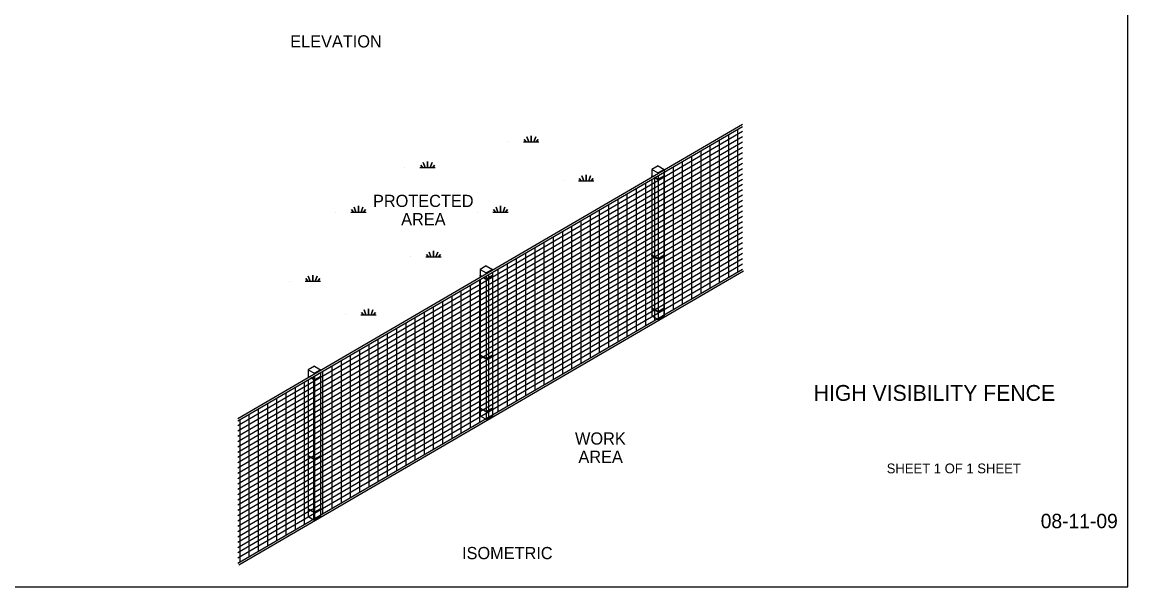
# Model space of a CAD drawing. Extents: x 99862 to 103151, y 100000 to 102076.
# Drawn here: x 101337 to 103151, y 100000 to 100926 of the extents above; entities that cross this region are included whole.
import ezdxf

# ---------------------------------------------------------------- set-up
doc = ezdxf.new("R2010")
doc.units = 0
for name, color, linetype in [('Level 1', 7, 'Continuous'), ('Level 10', 7, 'Continuous'), ('Level 11', 7, 'Continuous'), ('Level 15', 7, 'Continuous'), ('Level 20', 7, 'Continuous'), ('Level 31', 7, 'Continuous'), ('Level 38', 7, 'Continuous'), ('Level 62', 7, 'Continuous'), ('Level 9', 7, 'Continuous')]:
    doc.layers.add(name, color=color, linetype=linetype)

msp = doc.modelspace()

# ---------------------------------------------------------------- linework, layer by layer
at = {"layer": 'Level 1'}
msp.add_lwpolyline([(99862, 99999.5), (103151, 99999.5), (103151, 102075.5), (99862, 102075.5)], close=True, dxfattribs=at)
at = {"layer": 'Level 10'}
msp.add_line((101815.7, 100208.6), (101815.7, 100208.7), dxfattribs=at)
at = {"layer": 'Level 11'}
for p, q in [((102372.4, 100672.9), (102370.3, 100674.1)), ((102370.3, 100673.4), (102370.3, 100674.1)), ((102371.7, 100672.6), (102370.3, 100673.4)), ((102380.3, 100667.6), (102374.5, 100670.9)), ((102380.3, 100668.3), (102375.2, 100671.3)), ((102390.3, 100674.1), (102380.3, 100668.3)), ((102390.3, 100673.4), (102380.3, 100667.6)), ((102390.3, 100673.4), (102390.3, 100674.1)), ((102380.3, 100538), (102370.3, 100543.7)), ((102370.3, 100543), (102370.3, 100543.7)), ((102380.3, 100537.2), (102370.3, 100543)), ((102390.3, 100543.7), (102380.3, 100538)), ((102390.3, 100543), (102380.3, 100537.2)), ((102390.3, 100543), (102390.3, 100543.7)), ((102091, 100508.8), (102088.5, 100510.2)), ((102088.5, 100509.5), (102088.5, 100510.2)), ((102098.5, 100503.7), (102093.3, 100506.7)), ((102098.5, 100504.5), (102093.9, 100507.1)), ((102108.5, 100510.2), (102098.5, 100504.5)), ((102108.5, 100509.5), (102098.5, 100503.7)), ((102108.5, 100509.5), (102108.5, 100510.2)), ((102380.3, 100451), (102370.3, 100456.8)), ((102370.3, 100456.8), (102370.3, 100456.1)), ((102380.3, 100450.3), (102370.3, 100456.1)), ((102390.3, 100456.8), (102380.3, 100451)), ((102390.3, 100456.1), (102380.3, 100450.3)), ((102390.3, 100456.1), (102390.3, 100456.8)), ((102098.5, 100374.1), (102088.5, 100379.9)), ((102108.5, 100379.9), (102098.5, 100374.1)), ((102108.5, 100379.1), (102108.5, 100379.9)), ((102098.5, 100373.4), (102088.5, 100379.1)), ((102108.5, 100379.1), (102098.5, 100373.4)), ((101808.4, 100344), (101806.6, 100345)), ((101807.8, 100343.6), (101806.6, 100344.3)), ((101826.6, 100345), (101816.6, 100339.2)), ((101826.6, 100344.3), (101816.6, 100338.5)), ((101826.6, 100344.3), (101826.6, 100345)), ((101816.6, 100338.5), (101810.8, 100341.9)), ((101816.6, 100339.2), (101811.4, 100342.3)), ((102098.5, 100287.2), (102088.5, 100293)), ((102088.5, 100292.2), (102088.5, 100293)), ((102098.5, 100286.5), (102088.5, 100292.2)), ((102108.5, 100293), (102098.5, 100287.2)), ((102108.5, 100292.2), (102098.5, 100286.5)), ((102108.5, 100292.2), (102108.5, 100293)), ((101810, 100212.7), (101806.6, 100214.7)), ((101806.6, 100213.9), (101806.6, 100214.7)), ((101809.4, 100212.3), (101806.6, 100213.9)), ((101816.6, 100208.2), (101810.6, 100211.6)), ((101816.6, 100208.9), (101811.3, 100212)), ((101826.6, 100214.7), (101816.6, 100208.9)), ((101826.6, 100213.9), (101816.6, 100208.2)), ((101826.6, 100213.9), (101826.6, 100214.7)), ((101816.6, 100122), (101806.6, 100127.7)), ((101806.6, 100127.7), (101806.6, 100127)), ((101816.6, 100121.2), (101806.6, 100127)), ((101826.6, 100127.7), (101816.6, 100122)), ((101826.6, 100127), (101816.6, 100121.2)), ((101826.6, 100127), (101826.6, 100127.7))]:
    msp.add_line(p, q, dxfattribs=at)
at = {"layer": 'Level 31'}
for p, q in [((102134.8, 100729.7), (102134.8, 100729.7)), ((101964.8, 100687.7), (101964.8, 100687.7)), ((102225, 100665.8), (102225, 100665.8)), ((101851.5, 100614.6), (101851.5, 100614.6)), ((102084.3, 100614.6), (102084.3, 100614.6)), ((101974.4, 100540.9), (101974.4, 100540.9)), ((101776.4, 100501.3), (101776.4, 100501.3)), ((101867.9, 100446), (101867.9, 100446))]:
    msp.add_line(p, q, dxfattribs=at)
for points in [[(102159.8, 100729.7), (102164, 100729.7), (102160.9, 100733.7), (102164, 100729.7), (102168.1, 100729.7), (102165, 100737.8), (102168.1, 100729.7), (102172.3, 100729.7), (102172.3, 100739.7), (102172.3, 100729.7), (102176.5, 100729.7), (102179.6, 100737.8), (102176.5, 100729.7), (102180.6, 100729.7), (102183.7, 100733.7), (102180.6, 100729.7), (102184.8, 100729.7)], [(101989.8, 100687.7), (101994, 100687.7), (101990.9, 100691.7), (101994, 100687.7), (101998.1, 100687.7), (101995, 100695.8), (101998.1, 100687.7), (102002.3, 100687.7), (102002.3, 100697.6), (102002.3, 100687.7), (102006.5, 100687.7), (102009.6, 100695.8), (102006.5, 100687.7), (102010.6, 100687.7), (102013.7, 100691.7), (102010.6, 100687.7), (102014.8, 100687.7)], [(102249.9, 100665.8), (102254.1, 100665.8), (102251, 100669.9), (102254.1, 100665.8), (102258.3, 100665.8), (102255.2, 100673.9), (102258.3, 100665.8), (102262.4, 100665.8), (102262.4, 100675.8), (102262.4, 100665.8), (102266.6, 100665.8), (102269.7, 100673.9), (102266.6, 100665.8), (102270.8, 100665.8), (102273.9, 100669.9), (102270.8, 100665.8), (102274.9, 100665.8)], [(101876.5, 100614.6), (101880.7, 100614.6), (101877.6, 100618.6), (101880.7, 100614.6), (101884.8, 100614.6), (101881.7, 100622.7), (101884.8, 100614.6), (101889, 100614.6), (101889, 100624.6), (101889, 100614.6), (101893.1, 100614.6), (101896.3, 100622.7), (101893.1, 100614.6), (101897.3, 100614.6), (101900.4, 100618.6), (101897.3, 100614.6), (101901.5, 100614.6)], [(102109.3, 100614.6), (102113.5, 100614.6), (102110.4, 100618.6), (102113.5, 100614.6), (102117.6, 100614.6), (102114.5, 100622.7), (102117.6, 100614.6), (102121.8, 100614.6), (102121.8, 100624.6), (102121.8, 100614.6), (102126, 100614.6), (102129.1, 100622.7), (102126, 100614.6), (102130.1, 100614.6), (102133.2, 100618.6), (102130.1, 100614.6), (102134.3, 100614.6)], [(101999.4, 100540.9), (102003.5, 100540.9), (102000.4, 100544.9), (102003.5, 100540.9), (102007.7, 100540.9), (102004.6, 100549), (102007.7, 100540.9), (102011.9, 100540.9), (102011.9, 100550.8), (102011.9, 100540.9), (102016, 100540.9), (102019.1, 100549), (102016, 100540.9), (102020.2, 100540.9), (102023.3, 100544.9), (102020.2, 100540.9), (102024.4, 100540.9)], [(101801.4, 100501.3), (101805.6, 100501.3), (101802.5, 100505.3), (101805.6, 100501.3), (101809.7, 100501.3), (101806.6, 100509.4), (101809.7, 100501.3), (101813.9, 100501.3), (101813.9, 100511.2), (101813.9, 100501.3), (101818, 100501.3), (101821.2, 100509.4), (101818, 100501.3), (101822.2, 100501.3), (101825.3, 100505.3), (101822.2, 100501.3), (101826.4, 100501.3)], [(101892.9, 100446), (101897, 100446), (101893.9, 100450), (101897, 100446), (101901.2, 100446), (101898.1, 100454.1), (101901.2, 100446), (101905.4, 100446), (101905.4, 100455.9), (101905.4, 100446), (101909.5, 100446), (101912.6, 100454.1), (101909.5, 100446), (101913.7, 100446), (101916.8, 100450), (101913.7, 100446), (101917.9, 100446)]]:
    msp.add_lwpolyline(points, dxfattribs=at)
at = {"layer": 'Level 38'}
for p, q in [((102380.3, 100690.4), (102370.3, 100684.6)), ((102380.3, 100690.4), (102390.3, 100684.6)), ((102370.3, 100684.6), (102380.3, 100678.8)), ((102370.3, 100684.6), (102370.3, 100671.7)), ((102390.3, 100684.6), (102380.3, 100678.8)), ((102380.3, 100678.8), (102380.3, 100677.5)), ((102380.3, 100674.3), (102380.3, 100668.3)), ((102390.3, 100684.6), (102390.3, 100683.4)), ((102390.3, 100683.4), (102390.3, 100674.1)), ((102390.3, 100673.4), (102390.3, 100543.7)), ((102370.3, 100668.2), (102370.3, 100543.7)), ((102380.3, 100667.6), (102380.3, 100538)), ((102370.3, 100543), (102370.3, 100456.8)), ((102390.3, 100543), (102390.3, 100456.8)), ((102098.5, 100526.2), (102088.5, 100520.5)), ((102098.5, 100526.2), (102108.5, 100520.5)), ((102380.3, 100537.2), (102380.3, 100451)), ((102088.5, 100520.5), (102098.5, 100514.7)), ((102088.5, 100520.5), (102088.5, 100507.4)), ((102108.5, 100520.5), (102098.5, 100514.7)), ((102098.5, 100514.7), (102098.5, 100513.2)), ((102098.5, 100509.9), (102098.5, 100504.5)), ((102108.5, 100520.5), (102108.5, 100519)), ((102108.5, 100515.5), (102108.5, 100379.9)), ((102088.5, 100504.1), (102088.5, 100280.2)), ((102098.5, 100503.7), (102098.5, 100374.1)), ((102370.3, 100456.1), (102370.3, 100444.1)), ((102390.3, 100456.1), (102390.3, 100446.2)), ((102370.3, 100444.1), (102378.6, 100439.4)), ((102379.4, 100438.8), (102380.3, 100438.3)), ((102380.3, 100450.3), (102380.3, 100440.4)), ((102390.3, 100444.1), (102380.3, 100438.3)), ((102380.3, 100439.4), (102380.3, 100438.3)), ((102390.3, 100445.2), (102390.3, 100444.1)), ((102098.5, 100373.4), (102098.5, 100287.2)), ((102108.5, 100379.1), (102108.5, 100293)), ((101816.6, 100361.6), (101806.6, 100355.8)), ((101806.6, 100355.8), (101816.6, 100350)), ((101806.6, 100355.8), (101806.6, 100343)), ((101816.6, 100361.6), (101826.6, 100355.8)), ((101826.6, 100355.8), (101816.6, 100350)), ((101816.6, 100350), (101816.6, 100348.8)), ((101816.6, 100345.6), (101816.6, 100339.2)), ((101826.6, 100355.8), (101826.6, 100354.7)), ((101826.6, 100351.4), (101826.6, 100343.9)), ((101806.6, 100339.7), (101806.6, 100127.7)), ((101816.6, 100338.5), (101816.6, 100208.9)), ((101826.6, 100342.5), (101826.6, 100214.7)), ((102108.5, 100292.2), (102108.5, 100281.8)), ((102088.5, 100280.2), (102096.4, 100275.6)), ((102097.9, 100274.7), (102098.5, 100274.4)), ((102098.5, 100286.5), (102098.5, 100276)), ((102108.5, 100280.2), (102098.5, 100274.4)), ((102098.5, 100275), (102098.5, 100274.4)), ((102108.5, 100280.8), (102108.5, 100280.2)), ((101816.6, 100208.2), (101816.6, 100122)), ((101826.6, 100213.9), (101826.6, 100127.7)), ((101806.6, 100127), (101806.6, 100115.2)), ((101826.6, 100127), (101826.6, 100117.5)), ((101806.6, 100114.9), (101816.6, 100109.1)), ((101815.4, 100109.9), (101816.6, 100109.1)), ((101816.6, 100121.2), (101816.6, 100111.6)), ((101826.6, 100114.9), (101816.6, 100109.1)), ((101816.6, 100110.6), (101816.6, 100109.1)), ((101826.6, 100116.5), (101826.6, 100114.9))]:
    msp.add_line(p, q, dxfattribs=at)
at = {"layer": 'Level 9'}
for p, q in [((102518.7, 100758.3), (101690.9, 100275.5)), ((101690.9, 100272.2), (102518.7, 100755)), ((101690.9, 100264.3), (102518.7, 100747.1)), ((102510.8, 100750.4), (102510.8, 100516.5)), ((101690.9, 100255.6), (102518.7, 100738.4)), ((101690.9, 100246.9), (102518.7, 100729.7)), ((102480.5, 100732.7), (102480.5, 100498.8)), ((102495.6, 100741.6), (102495.6, 100507.6)), ((101690.9, 100238.2), (102518.7, 100721)), ((101690.9, 100229.5), (102518.7, 100712.3)), ((102435.1, 100706.3), (102435.1, 100472.3)), ((102450.3, 100715.1), (102450.3, 100481.2)), ((102450.3, 100715.1), (102450.3, 100658.3)), ((102465.4, 100723.9), (102465.4, 100490)), ((102465.4, 100723.9), (102465.4, 100667.2)), ((101690.9, 100220.8), (102518.7, 100703.6)), ((101690.9, 100212.1), (102518.7, 100694.9)), ((102404.9, 100688.6), (102404.9, 100454.7)), ((102420, 100697.5), (102420, 100463.5)), ((101690.9, 100203.4), (102518.7, 100686.2)), ((101690.9, 100194.8), (102518.7, 100677.5)), ((102374.6, 100671), (102374.6, 100437.1)), ((102389.8, 100679.8), (102389.8, 100445.9)), ((101690.9, 100186.1), (102518.7, 100668.8)), ((101690.9, 100177.4), (102518.7, 100660.2)), ((102344.4, 100653.4), (102344.4, 100419.4)), ((102359.5, 100662.2), (102359.5, 100428.2)), ((101690.9, 100168.7), (102518.7, 100651.5)), ((101690.9, 100160), (102518.7, 100642.8)), ((101690.9, 100151.3), (102518.7, 100634.1)), ((102314.1, 100635.7), (102314.1, 100401.8)), ((102314.1, 100635.7), (102314.1, 100578.9)), ((102329.3, 100644.5), (102329.3, 100410.6)), ((101690.9, 100142.6), (102518.7, 100625.4)), ((101690.9, 100133.9), (102518.7, 100616.7)), ((102283.9, 100618.1), (102283.9, 100384.1)), ((102283.9, 100618.1), (102283.9, 100561.3)), ((102299, 100626.9), (102299, 100393)), ((102299, 100626.9), (102299, 100570.1)), ((101690.9, 100125.2), (102518.7, 100608)), ((101690.9, 100116.5), (102518.7, 100599.3)), ((102253.6, 100600.4), (102253.6, 100366.5)), ((102268.8, 100609.3), (102268.8, 100375.3)), ((101690.9, 100107.8), (102518.7, 100590.6)), ((101690.9, 100099.2), (102518.7, 100581.9)), ((102223.4, 100582.8), (102223.4, 100348.9)), ((102238.5, 100591.6), (102238.5, 100357.7)), ((101690.9, 100090.5), (102518.7, 100573.2)), ((101690.9, 100081.8), (102518.7, 100564.5)), ((102193.1, 100565.1), (102193.1, 100331.2)), ((102208.3, 100574), (102208.3, 100340)), ((101690.9, 100073.1), (102518.7, 100555.9)), ((101690.9, 100064.4), (102518.7, 100547.2)), ((102162.9, 100547.5), (102162.9, 100313.6)), ((102178, 100556.3), (102178, 100322.4)), ((101690.9, 100055.7), (102518.7, 100538.5)), ((101690.9, 100047), (102518.7, 100529.8)), ((102132.6, 100529.9), (102132.6, 100295.9)), ((102147.8, 100538.7), (102147.8, 100304.8)), ((101690.9, 100038.3), (102518.7, 100521.1)), ((101692.5, 100035.5), (102520.4, 100518.3)), ((102102.4, 100512.2), (102102.4, 100278.3)), ((102117.5, 100521), (102117.5, 100287.1)), ((102072.1, 100494.6), (102072.1, 100260.7)), ((102087.3, 100503.4), (102087.3, 100269.5)), ((102041.9, 100476.9), (102041.9, 100243)), ((102057, 100485.8), (102057, 100251.8)), ((102011.6, 100459.3), (102011.6, 100225.4)), ((102011.6, 100459.3), (102011.6, 100402.5)), ((102026.8, 100468.1), (102026.8, 100234.2)), ((101981.4, 100441.7), (101981.4, 100207.7)), ((101981.4, 100441.7), (101981.4, 100384.9)), ((101996.5, 100450.5), (101996.5, 100216.5)), ((101996.5, 100450.5), (101996.5, 100393.7)), ((101951.1, 100424), (101951.1, 100190.1)), ((101966.3, 100432.8), (101966.3, 100198.9)), ((101920.9, 100406.4), (101920.9, 100172.4)), ((101936, 100415.2), (101936, 100181.3)), ((101875.5, 100379.9), (101875.5, 100146)), ((101890.6, 100388.7), (101890.6, 100154.8)), ((101905.8, 100397.6), (101905.8, 100163.6)), ((101845.3, 100362.3), (101845.3, 100128.3)), ((101860.4, 100371.1), (101860.4, 100137.2)), ((101815, 100344.6), (101815, 100110.7)), ((101830.1, 100353.5), (101830.1, 100119.5)), ((101784.8, 100327), (101784.8, 100093.1)), ((101799.9, 100335.8), (101799.9, 100101.9)), ((101754.5, 100309.3), (101754.5, 100075.4)), ((101769.6, 100318.2), (101769.6, 100084.2)), ((101724.3, 100291.7), (101724.3, 100057.8)), ((101739.4, 100300.5), (101739.4, 100066.6)), ((101694, 100274.1), (101694, 100040.1)), ((101694, 100274.1), (101694, 100217.3)), ((101709.2, 100282.9), (101709.2, 100049)), ((101709.2, 100282.9), (101709.2, 100226.1))]:
    msp.add_line(p, q, dxfattribs=at)

# ---------------------------------------------------------------- texts
at = {"layer": 'Level 1'}
msp.add_text('08-11-09', height=23.62, dxfattribs=at).set_placement((103008, 100095.8))
at = {"layer": 'Level 15'}
for s, p in [('PROTECTED', (101912.7, 100622.9)), ('AREA', (101958.9, 100592.9)), ('WORK', (102244.1, 100233)), ('AREA', (102249.7, 100203))]:
    msp.add_text(s, height=20, dxfattribs=at).set_placement(p)
at = {"layer": 'Level 20'}
for s, p in [('ELEVATION', (101777, 100884.7)), ('ISOMETRIC', (102058.8, 100045))]:
    msp.add_text(s, height=20, dxfattribs=at).set_placement(p)
at = {"layer": 'Level 62'}
for s, height, p in [('HIGH VISIBILITY FENCE', 26, (102635.6, 100304.8)), ('SHEET 1 OF 1 SHEET', 16, (102755.4, 100185.9))]:
    msp.add_text(s, height=height, dxfattribs=at).set_placement(p)

doc.saveas('drawing.dxf')
